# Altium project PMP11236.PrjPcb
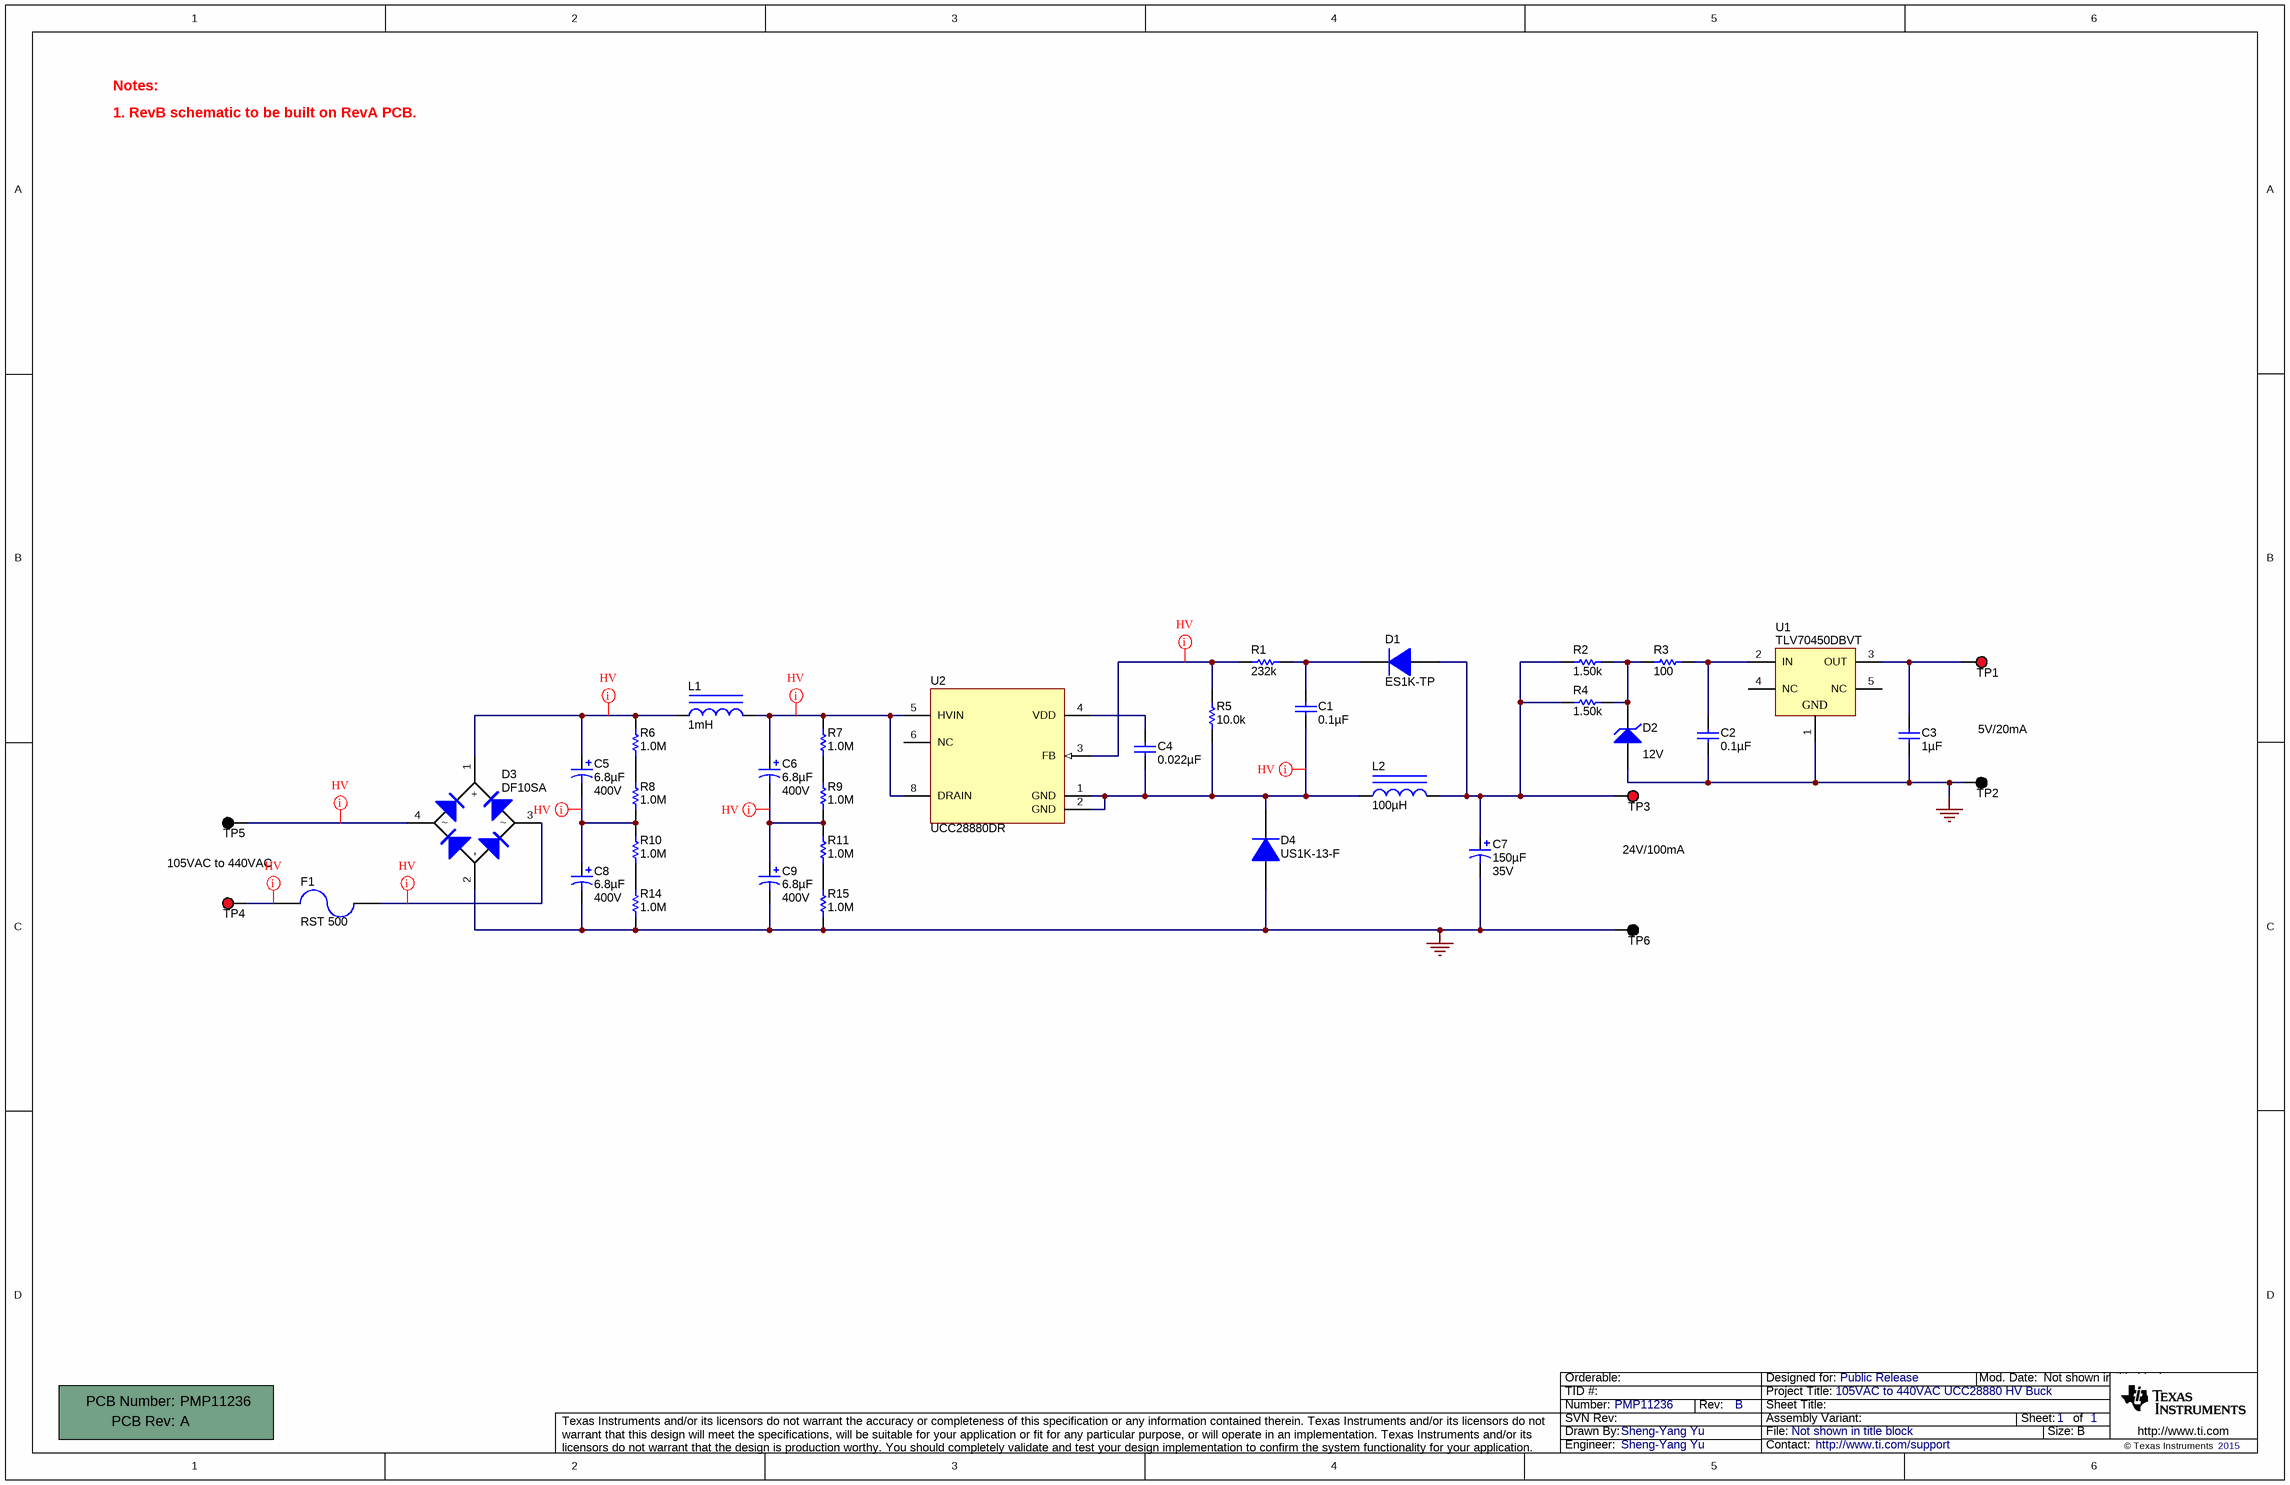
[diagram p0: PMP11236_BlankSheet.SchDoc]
TechSupport: http://www.ti.com/support; SCH_Rev: B; PRJ_Title: 105VAC to 440VAC UCC28880 HV Buck; PRJ_Number: PMP11236; PRJ_Engineer: Sheng-Yang Yu; PRJ_Customer: Public Release; PCB_Rev: A; PCB_Layout: Sheng-Yang Yu; CopyrightYear: 2015
1 sheet, 38 parts. Net scope: global (net labels, ports and power ports of the same name join across sheets).
Board file: PMP11236_TID.PcbDoc

## Sheet PMP11236_BlankSheet.SchDoc
size 431 x 279 mm; Date: Not shown in title block; ApprovedBy: Not shown in title block; CheckedBy: Not shown in title block; Author: Not shown in title block; CompanyName: Not shown in title block; DrawnBy: Sheng-Yang Yu; Engineer: Not shown in title block; Organization: Not shown in title block; Address1: Not shown in title block; Address2: Not shown in title block; Address3: Not shown in title block; Address4: Not shown in title block; DocumentNumber: 1; Revision: Use project parameter SCH_Rev; SheetNumber: 1; SheetTotal: 1; PageSetup: Record=PageOptions¦CenterHorizontal=True¦CenterVertical=True¦PrintScale=1.00¦XCorrection=1.00¦YCorrection=1.00¦PrintKind=0¦BorderSize=5000000¦LeftOffset=0¦BottomOffset=0¦Orientation=2¦PaperLength=1000¦PaperWidth=1000¦Scale=100¦PaperSource=15¦PrintQuality=600¦MediaType=1¦DitherType=10¦PaperKind=Letter¦PrintScaleMode=1

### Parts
!PCB1  Printed Circuit Board  (value not drawn)  (mechanical)
C1  ValueDisplayed: 0.1µF  [1206]  (hidden comment: 12065C104JAT2A)
C2  ValueDisplayed: 0.1µF  [0603]  (hidden comment: 06033C104JAT2A)
C3  ValueDisplayed: 1µF  [0603]  (hidden comment: C0603C105K4PACTU)
C4  ValueDisplayed: 0.022µF  [1206]  (hidden comment: 12065C223KAT2A)
C5  ValueDisplayed: 6.8µF  Value2: 400V  [CAPPRD350W60D800H1100]  (hidden comment: 400AX6R8M8x11)
C6  ValueDisplayed: 6.8µF  Value2: 400V  [CAPPRD350W60D800H1100]  (hidden comment: 400AX6R8M8x11)
C7  ValueDisplayed: 150µF  Value2: 35V  [HE_800x1150]  (hidden comment: UPW1V151MPD)
C8  ValueDisplayed: 6.8µF  Value2: 400V  [CAPPRD350W60D800H1100]  (hidden comment: 400AX6R8M8x11)
C9  ValueDisplayed: 6.8µF  Value2: 400V  [CAPPRD350W60D800H1100]  (hidden comment: 400AX6R8M8x11)
D1  ES1K-TP  [SMA]
D2  value 12V  [SMA]  (hidden comment: 1SMA5927BT3G)
D3  DF10SA  [DF-S]
D4  US1K-13-F  [SMA]
F1  RST 500  [Fuse_RST]
L1  ValueDisplayed: 1mH  [WE-TI_5075]  (hidden comment: 7447462102)
L2  ValueDisplayed: 100µH  [WE-TI_8055]  (hidden comment: 744741101)
R1  ValueDisplayed: 232k  [0603]  (hidden comment: CRCW0603232KFKEA)
R2  ValueDisplayed: 1.50k  [1206]  (hidden comment: CRCW12061K50FKEA)
R3  ValueDisplayed: 100  [1206]  (hidden comment: CRCW1206100RFKEA)
R4  ValueDisplayed: 1.50k  [1206]  (hidden comment: CRCW12061K50FKEA)
R5  value 10.0k  [0603]  (hidden comment: CRCW060310K0FKEA)
R6  ValueDisplayed: 1.0M  [0603]  (hidden comment: CRCW06031M00JNEA)
R7  ValueDisplayed: 1.0M  [0603]  (hidden comment: CRCW06031M00JNEA)
R8  ValueDisplayed: 1.0M  [0603]  (hidden comment: CRCW06031M00JNEA)
R9  ValueDisplayed: 1.0M  [0603]  (hidden comment: CRCW06031M00JNEA)
R10  ValueDisplayed: 1.0M  [0603]  (hidden comment: CRCW06031M00JNEA)
R11  ValueDisplayed: 1.0M  [0603]  (hidden comment: CRCW06031M00JNEA)
R14  ValueDisplayed: 1.0M  [0603]  (hidden comment: CRCW06031M00JNEA)
R15  ValueDisplayed: 1.0M  [0603]  (hidden comment: CRCW06031M00JNEA)
TP1  5000  [Keystone5000]  (value not drawn)
TP2  5001  [Keystone5001]  (value not drawn)
TP3  5000  [Keystone5000]  (value not drawn)
TP4  5000  [Keystone5000]  (value not drawn)
TP5  5001  [Keystone5001]  (value not drawn)
TP6  5001  [Keystone5001]  (value not drawn)
U1  TLV70450DBVT  [DBV0005A_N]
U2  UCC28880DR  [D0007A_N]

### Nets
GND: C2.2 C3.2 C7.2(-) C8.2(-) C9.2(-) D2.2(A) D3.2(-) D4.2(A) R14.1 R15.1 TP2.1 TP6.1 U1.1(GND)
NetC1_1: C1.1 D1.1(K) R1.2
NetC1_2: C1.2 C4.2 D4.1(K) L2.1 R5.1 U2.1(GND) U2.2(GND)
NetC2_1: C2.1 R3.2 U1.2(IN)
NetC3_1: C3.1 TP1.1 U1.3(OUT)
NetC4_1: C4.1 U2.4(VDD)
NetC5_1: C5.1(+) D3.1(+) L1.1 R6.2
NetC5_2: C5.2(-) C8.1(+) R8.1 R10.2
NetC6_1: C6.1(+) L1.2 R7.2 U2.5(HVIN) U2.8(DRAIN)
NetC6_2: C6.2(-) C9.1(+) R9.1 R11.2
NetC7_1: C7.1(+) D1.2(A) L2.2 R2.1 R4.1 TP3.1
NetD2_1: D2.1(K) R2.2 R3.1 R4.2
NetD3_3: D3.3 F1.1
NetD3_4: D3.4 TP5.1
NetF1_2: F1.2 TP4.1
NetR1_1: R1.1 R5.2 U2.3(FB)
NetR6_1: R6.1 R8.2
NetR7_1: R7.1 R9.2
NetR10_1: R10.1 R14.2
NetR11_1: R11.1 R15.2

Not connected (* = marked no-connect by the designer): U1 4(NC) 5(NC); U2 6(NC)

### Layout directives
net class HV: NetC1_2, NetC5_1, NetC5_2, NetC6_1, NetC6_2, NetD3_3, NetD3_4, NetF1_2, NetR1_1

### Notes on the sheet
- Notes:
- 1. RevB schematic to be built on RevA PCB.
- 5V/20mA
- 105VAC to 440VAC
- 24V/100mA

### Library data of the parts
!PCB1 = PCB: Manufacturer: Any; PartNumber: PMP11236; SymbolCreator: a0412235
C1 = 12065C104JAT2A: CAP, CERM, 0.1uF, 50V, +/-5%, X7R, 1206; Manufacturer: AVX; Polarized: N; CompType: Capacitor; U/M: EA; Cap_F: 0.0000001; Tolerance_%: 5; ESR_Ohm: 0.037; Value1: 0.037 ohm; VDC_V: 50; TaMin_C: -55; TaMax_C: 125
C2 = 06033C104JAT2A: CAP, CERM, 0.1 µF, 25 V, +/- 5%, X7R, 0603; Manufacturer: AVX; Polarized: N; CompType: Capacitor; Value: 0.1uF; U/M: EA; Cap_F: 0.0000001; Tolerance_%: 5; ESR_ohm: 0.05; Value1: 0.05 ohm; VDC_V: 25; Value2: 25V; TaMin_C: -55; TaMax_C: 125
C3 = C0603C105K4PACTU: CAP, CERM, 1 µF, 16 V, +/- 10%, X5R, 0603; Manufacturer: Kemet; Polarized: N; CompType: Capacitor; Value: 1uF; U/M: EA; Cap_F: 0.000001; Tolerance_%: 10; Value1: Unknown; VDC_V: 16; Value2: 16V; TaMin_C: -55; TaMax_C: 85
C4 = 12065C223KAT2A: CAP, CERM, 0.022uF, 50V, +/-10%, X7R, 1206; Manufacturer: AVX; Polarized: N; CompType: Capacitor; U/M: EA; Cap_F: 0.000000022; Tolerance_%: 10; ESR_Ohm: 0.079; Value1: 0.079 ohm; VDC_V: 50; TaMin_C: -55; TaMax_C: 125
C5 C6 C8 C9 = 400AX6R8M8x11: CAP, AL, 6.8 µF, 400 V, +/- 20%, TH; Manufacturer: Rubycon; Polarized: Y; CompType: Capacitor; Value: 6.8uF; U/M: EA; Cap_F: 0.0000068; Tolerance_%: 20; Value1: Unknown; VDC_V: 400; TaMin_C: -40; TaMax_C: 105; Cap_Case: 8x11
C7 = UHE1H101MPD: CAP ALUM 150UF 35V 20% RADIAL; Manufacturer: Nichicon; Polarized: Y; CompType: Capacitor; U/M: EA; Cap_F: 0.0001; Tolerance_%: 20; Value1: 0.17 ohm; VDC_V: 35; ESR_ohm: 0.17; IRMS_A: 0.555; TaMin_C: -40; TaMax_C: 105; Cap_Case: 8x11.5
D1 = ES1D-13-F: DIODE GEN PURP 800V 1A DO214AC; Manufacturer: Diodes Inc.; U/M: EA; Io_A: 1; Vr_V: 800; TJmax_C: 150; RJC_CperW: 25; Type: Ultrafast
D2 = 1SMA5927BT3G: Diode, Zener, 12 V, 1.5 W, SMA; Manufacturer: ON Semiconductor; SymbolCreator: a0412235; U/M: EA; Power_W: 1.5; Vz_V: 12; Value1: 1.5W; RJA_CperW: 250
D3 = DF10SA: Diode, Switching-Bridge, 1000 V, 1 A, DF-S; Manufacturer: Vishay-Semiconductor; U/M: EA; Vf_V: 1.1; Value: 1000V; Value1: 1A; Value2: 1.1V; Io_A: 1; Vr_V: 1000; TJmax_C: 150; RJC_CperW: 15
D4 = US1K-13-F: Diode, Fast Rectifier, 800 V, 1 A, SMA; Manufacturer: Diodes Inc.; U/M: EA; Vf_V: 1.7; Value: 800V; Value1: 1A; Value2: 1.7V; Io_A: 1; Vr_V: 800; TJmax_C: 150
F1 = RST 500: Fuse, 0.5 A, 250 V, TH; Manufacturer: Bel Fuse; U/M: EA; OpeningTime_100%_min: 1; OpeningTime_200%_max: 120; VDC_V: 250; Irating_A: 0.5; Rtyp_Ohm: 0.18; MeltingTyp: 1.7; Vdrop: 0.114; Soldering_Wave_MaxTemp_C: 260; Soldering_Wave_MaxTime_s: 10
L1 = 7447462102: Inductor, Unshielded Drum Core, Ferrite, 1 mH, 0.25 A, 4.38 ohm, TH; Manufacturer: Wurth Elektronik; Value: 1mH; Ind_H: 1.0E-3; Imax_A: 0.25; Irms: 0.25A @ 40C rise; Isat: 0.27A @ 10% inductance drop; DCR_ohm: 4.38; Value2: 0.25A
L2 = 744741101: Inductor, Wirewound, Ferrite, 100 µH, 1.1 A, 0.39 ohm, TH; Manufacturer: Wurth Elektronik; Value: 100uH; Ind_H: 100.0E-6; Imax_A: 1.1; Irms: 1.1A @ 40C rise; Isat: 0.9A @ 10% inductance drop; DCR_ohm: 0.39; Value2: 1.1A
R1 = CRCW0603232KFKEA: RES, 232 k, 1%, 0.1 W, 0603; Manufacturer: Vishay-Dale; CompType: Resistor; Value: 232k; Res_ohm: 232000; Tolerance_%: 1; Power_W: 0.1; Value2: 0.1W; VDC_V: 75; TempCo: 100 ppm/C; EIA_Code: E96; U/M: EA
R2 R4 = CRCW12061K50FKEA: RES, 1.50 k, 1%, 0.25 W, 1206; Manufacturer: Vishay-Dale; CompType: Resistor; Value: 1.50k; Res_ohm: 1500; Value_Code: 1k50; Tolerance_%: 1; Power_W: 0.25; Value2: 0.25W; VDC_V: 200; TempCo: 100 ppm/C; EIA_Code: E96; U/M: EA
R3 = CRCW1206100RFKEA: RES, 100, 1%, 0.25 W, 1206; Manufacturer: Vishay-Dale; CompType: Resistor; Value: 100; Value_Code: 100R; Tolerance_%: 1; Power_W: 0.25; Value2: 0.25W; VDC_V: 200; TempCo: 100 ppm/C; EIA_Code: E96; U/M: EA
R5 = CRCW060310K0FKEA: RES, 10.0k ohm, 1%, 0.1W, 0603; Manufacturer: Vishay-Dale; CompType: Resistor; Res_ohm: 10000; Value_Code: 10k0; Tolerance_%: 1; Power_W: 0.1; VDC_V: 75; TempCo: 100 ppm/C; EIA_Code: E96; U/M: EA
R6-R11 R14 R15 = CRCW06031M00JNEA: RES, 1.0 M, 5%, 0.1 W, 0603; Manufacturer: Vishay-Dale; CompType: Resistor; Value: 1.0Meg; Res_ohm: 1000000; Value_Code: 1M00; Tolerance_%: 5; Power_W: 0.1; Value2: 0.1W; VDC_V: 75; TempCo: 200 ppm/C; EIA_Code: E24; U/M: EA
TP1 TP3 TP4 = 5000: Test Point, Miniature, Red, TH; Manufacturer: Keystone; CompType: Test Point Loop; U/M: EA
TP2 TP5 TP6 = 5001: Test Point, Miniature, Black, TH; Manufacturer: Keystone; CompType: Test Point Loop; U/M: EA
U1 = TLV70450DBVT: Single Output LDO, 150 mA, Fixed 5 V Output, 2.5 to 24 V Input, with Ultra-Low IQ, 5-pin SOT-23 (DBV), -40 to 125 degC, Green (RoHS & no Sb/Br); Manufacturer: Texas Instruments; Alternate Manufacturer: None; Alternate PartNumber: Equivalent; Accuracy(%): 2; Fixed Output Options(V): 5; Iout(Max)(A): 0.15; Iq(Typ)(mA): 0.003; SubFamily: Single Channel LDO; Vdo(Typ)(mV): 400; Vin(Max)(V): 24; Vin(Min)(V): 2.5
U2 = UCC28880DR: 700-V Lowest Quiescent Current Off-Line Switcher, D0007A; Manufacturer: Texas Instruments; SymbolCreator: a0411947; CompType: IC; U/M: EA

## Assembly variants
001: not fitted FID1 FID2 FID3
